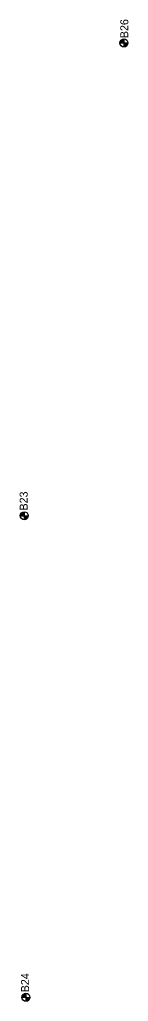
# Model space of a CAD drawing. Extents: x 345549 to 379569, y 127949 to 230467.
# Drawn here: x 361587 to 361723, y 140934 to 142161 of the extents above; entities that cross this region are included whole.
import ezdxf

# ---------------------------------------------------------------- set-up
doc = ezdxf.new("R2010")
doc.units = 0
for name, color, linetype in [('E_SOIL_BORE1 [KAPUR_CADDS_LEVELS]', 7, 'Continuous'), ('E_SOIL_BORE2 [KAPUR_CADDS_LEVELS]', 7, 'Continuous'), ('P_MARK', 7, 'Continuous')]:
    doc.layers.add(name, color=color, linetype=linetype)

msp = doc.modelspace()

# ---------------------------------------------------------------- linework, layer by layer
at = {"layer": 'P_MARK'}
for p, q in [((361712.8, 142131.6), (361722.8, 142131.6)), ((361717.8, 142136.6), (361717.8, 142126.6)), ((361588.1, 141541), (361598.1, 141541)), ((361593.1, 141546), (361593.1, 141536)), ((361590.2, 140939.4), (361600.2, 140939.3)), ((361595.2, 140944.3), (361595.2, 140934.4))]:
    msp.add_line(p, q, dxfattribs=at)
for centre in [(361717.8, 142131.6), (361593.1, 141541), (361595.2, 140939.4)]:
    msp.add_circle(centre, 5, dxfattribs=at)
for centre, radius, start, end in [((361717.8, 142131.6), 4.5, 89.9869, 179.9869), ((361717.8, 142131.6), 4, 89.9869, 179.9869), ((361717.8, 142131.6), 3.5, 89.9869, 179.9869), ((361717.8, 142131.6), 3, 89.9869, 179.9869), ((361717.8, 142131.6), 2.5, 89.9869, 179.9869), ((361717.8, 142131.6), 2, 89.9869, 179.9869), ((361717.8, 142131.6), 1.5, 89.9869, 179.9869), ((361717.8, 142131.6), 1, 89.9869, 179.9869), ((361717.8, 142131.6), 0.5, 89.9869, 179.9869), ((361717.8, 142131.6), 4.5, 269.9869, 359.9869), ((361717.8, 142131.6), 4, 269.9869, 359.9869), ((361717.8, 142131.6), 3.5, 269.9869, 359.9869), ((361717.8, 142131.6), 3, 269.9869, 359.9869), ((361717.8, 142131.6), 2.5, 269.9869, 359.9869), ((361717.8, 142131.6), 2, 269.9869, 359.9869), ((361717.8, 142131.6), 1.5, 269.9869, 359.9869), ((361717.8, 142131.6), 1, 269.9869, 359.9869), ((361717.8, 142131.6), 0.5, 269.9869, 359.9869), ((361593.1, 141541), 4.5, 89.9869, 179.9869), ((361593.1, 141541), 4, 89.9869, 179.9869), ((361593.1, 141541), 3.5, 89.9869, 179.9869), ((361593.1, 141541), 3, 89.9869, 179.9869), ((361593.1, 141541), 2.5, 89.9869, 179.9869), ((361593.1, 141541), 2, 89.9869, 179.9869), ((361593.1, 141541), 1.5, 89.9869, 179.9869), ((361593.1, 141541), 1, 89.9869, 179.9869), ((361593.1, 141541), 0.5, 89.9869, 179.9869), ((361593.1, 141541), 4.5, 269.9869, 359.9869), ((361593.1, 141541), 4, 269.9869, 359.9869), ((361593.1, 141541), 3.5, 269.9869, 359.9869), ((361593.1, 141541), 3, 269.9869, 359.9869), ((361593.1, 141541), 2.5, 269.9869, 359.9869), ((361593.1, 141541), 2, 269.9869, 359.9869), ((361593.1, 141541), 1.5, 269.9869, 359.9869), ((361593.1, 141541), 1, 269.9869, 359.9869), ((361593.1, 141541), 0.5, 269.9869, 359.9869), ((361595.2, 140939.4), 4.5, 89.9869, 179.9869), ((361595.2, 140939.4), 4, 89.9869, 179.9869), ((361595.2, 140939.4), 3.5, 89.9869, 179.9869), ((361595.2, 140939.4), 3, 89.9869, 179.9869), ((361595.2, 140939.4), 2.5, 89.9869, 179.9869), ((361595.2, 140939.4), 2, 89.9869, 179.9869), ((361595.2, 140939.4), 1.5, 89.9869, 179.9869), ((361595.2, 140939.4), 1, 89.9869, 179.9869), ((361595.2, 140939.4), 0.5, 89.9869, 179.9869), ((361595.2, 140939.4), 4.5, 269.9869, 359.9869), ((361595.2, 140939.4), 4, 269.9869, 359.9869), ((361595.2, 140939.4), 3.5, 269.9869, 359.9869), ((361595.2, 140939.4), 3, 269.9869, 359.9869), ((361595.2, 140939.4), 2.5, 269.9869, 359.9869), ((361595.2, 140939.4), 2, 269.9869, 359.9869), ((361595.2, 140939.4), 1.5, 269.9869, 359.9869), ((361595.2, 140939.4), 1, 269.9869, 359.9869), ((361595.2, 140939.4), 0.5, 269.9869, 359.9869)]:
    msp.add_arc(centre, radius, start, end, dxfattribs=at)

# ---------------------------------------------------------------- texts
at = {"layer": 'E_SOIL_BORE1 [KAPUR_CADDS_LEVELS]'}
for s, p in [('B23', (361597.4, 141547.5)), ('B24', (361599.1, 140945.7))]:
    msp.add_text(s, height=10, rotation=89.9869, dxfattribs=at).set_placement(p)
at = {"layer": 'E_SOIL_BORE2 [KAPUR_CADDS_LEVELS]'}
msp.add_text('B26', height=10, rotation=89.9869, dxfattribs=at).set_placement((361723.3, 142137.6))

doc.saveas('drawing.dxf')
